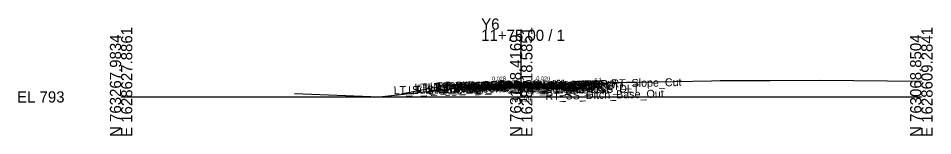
# Model space of a CAD drawing. Extents: x -26 to 203, y -10 to 6017.
# Drawn here: x -25.7 to 202.8, y 3490.3 to 3519.7 of the extents above; entities that cross this region are included whole.
import ezdxf

# ---------------------------------------------------------------- set-up
doc = ezdxf.new("R2010")
doc.units = 0
for name, color, linetype in [('Default', 7, 'Continuous'), ('Exist Cross Section Cell', 7, 'Continuous'), ('Exist XS Center Line Elevation Label', 7, 'Continuous'), ('Exist XS Ground Line', 7, 'Continuous'), ('Prop CMT Concrete Structures', 7, 'Continuous'), ('Prop CMT Pvmt Course 1', 7, 'Continuous'), ('Prop CMT Pvmt Course 2', 7, 'Continuous'), ('Prop CMT Pvmt Course 3', 7, 'Continuous'), ('Prop CMT Pvmt Surface', 7, 'Continuous'), ('Prop CMT Pvmt Surface Shoulder', 7, 'Continuous'), ('Prop CMT Pvmt Wedge Surface 2', 7, 'Continuous'), ('Prop CMT Pvmt Wedge Surface 3', 7, 'Continuous'), ('Prop CMT Shld Paved Course 1', 7, 'Continuous'), ('Prop CMT Shld Paved Course 2', 7, 'Continuous'), ('Prop CMT Shld Paved Course 3', 7, 'Continuous'), ('Prop CMT Slope Grass', 7, 'Continuous'), ('Prop CMT Subgrade Earthwork', 7, 'Continuous'), ('Prop XS SE Text', 7, 'Continuous'), ('Prop XS Side Slope Text', 7, 'Continuous'), ('Scratch_Level_0', 7, 'Continuous')]:
    doc.layers.add(name, color=color, linetype=linetype)

msp = doc.modelspace()

# ---------------------------------------------------------------- linework, layer by layer
at = {"layer": 'Exist Cross Section Cell'}
for p, q in [((100, 3500), (100, 3516.81)), ((0, 3500), (100, 3500)), ((100, 3500), (200, 3500))]:
    msp.add_line(p, q, dxfattribs=at)
at = {"layer": 'Exist XS Ground Line'}
msp.add_lwpolyline([(43.32, 3500.85), (64.56, 3500.04), (84.14, 3502.23), (89.22, 3502.94), (98.7, 3503.34), (100, 3503.39), (100.5, 3503.41), (102.9, 3503.38), (110.67, 3503.26), (112.66, 3503.27), (116.68, 3503.33), (124.6, 3503.6), (126.35, 3503.65), (128.35, 3503.71), (138.17, 3503.87), (147.55, 3504.05), (149.75, 3504.1), (162.15, 3504.13), (174.66, 3504.17), (200, 3503.98)], dxfattribs=at)
at = {"layer": 'Prop CMT Concrete Structures'}
msp.add_line((87, 3502.92), (82, 3503.02), dxfattribs=at)
for points in [[(87, 3502.92), (87, 3502.34), (89, 3502.34)], [(89, 3502.92), (88, 3502.84), (87, 3502.92)], [(89, 3502.34), (89, 3502.92)], [(111, 3502.42), (111, 3503.01)], [(113, 3503.01), (113, 3502.42), (111, 3502.42)], [(111, 3503.01), (112, 3502.92), (113, 3503.01)]]:
    msp.add_lwpolyline(points, dxfattribs=at)
at = {"layer": 'Prop CMT Pvmt Course 1'}
for points in [[(100, 3503.23), (89, 3502.92)], [(89, 3502.67), (100, 3502.98)], [(89, 3502.92), (89, 3502.67)], [(100, 3503.23), (89.22, 3502.93)], [(100, 3503.1), (100, 3503.23)], [(100, 3502.98), (100, 3503.23)], [(100, 3503.23), (110.67, 3503.01)], [(100, 3503.1), (100, 3503.23)], [(100, 3503.23), (111, 3503.01)], [(100, 3502.98), (100, 3503.23)], [(111, 3502.76), (100, 3502.98)], [(111, 3503.01), (111, 3502.76)]]:
    msp.add_lwpolyline(points, dxfattribs=at)
at = {"layer": 'Prop CMT Pvmt Course 2'}
for points in [[(100, 3502.98), (89, 3502.67)], [(89, 3502.67), (89, 3502.34)], [(89, 3502.34), (100, 3502.64)], [(100, 3502.64), (100, 3502.98)], [(100, 3502.64), (100, 3502.98)], [(100, 3502.98), (111, 3502.76)], [(111, 3502.42), (100, 3502.64)], [(111, 3502.76), (111, 3502.42)]]:
    msp.add_lwpolyline(points, dxfattribs=at)
at = {"layer": 'Prop CMT Pvmt Course 3'}
msp.add_line((113, 3502.42), (113.5, 3502.42), dxfattribs=at)
for points in [[(100, 3502.64), (89, 3502.34)], [(89, 3502.34), (89, 3502.01)], [(89, 3502.01), (100, 3502.31)], [(100, 3502.31), (100, 3502.64)], [(100, 3502.64), (111, 3502.42)], [(100, 3502.31), (100, 3502.64)], [(111, 3502.09), (100, 3502.31)], [(111, 3502.42), (111, 3502.09)]]:
    msp.add_lwpolyline(points, dxfattribs=at)
at = {"layer": 'Prop CMT Pvmt Surface'}
for points in [[(100, 3503.23), (89, 3502.92)], [(100, 3503.23), (89.22, 3502.93)], [(100, 3503.23), (111, 3503.01)], [(100, 3503.23), (110.67, 3503.01)]]:
    msp.add_lwpolyline(points, dxfattribs=at)
at = {"layer": 'Prop CMT Pvmt Surface Shoulder'}
for points in [[(89, 3502.92), (89, 3502.92)], [(111, 3503.01), (111, 3503.01)]]:
    msp.add_lwpolyline(points, dxfattribs=at)
at = {"layer": 'Prop CMT Pvmt Wedge Surface 2'}
for points in [[(100, 3502.98), (89.22, 3502.68)], [(100, 3502.98), (100, 3503.23)], [(100, 3502.98), (100, 3503.23)], [(100, 3502.98), (100, 3503.23)], [(100, 3502.98), (100, 3503.23)], [(100, 3502.98), (110.67, 3502.76)]]:
    msp.add_lwpolyline(points, dxfattribs=at)
at = {"layer": 'Prop CMT Pvmt Wedge Surface 3'}
for points in [[(100, 3502.64), (89.22, 3502.35)], [(100, 3502.64), (100, 3503.23)], [(100, 3502.64), (100, 3503.23)], [(100, 3502.64), (100, 3503.23)], [(100, 3502.64), (100, 3503.23)], [(100, 3502.64), (110.67, 3502.43)]]:
    msp.add_lwpolyline(points, dxfattribs=at)
at = {"layer": 'Prop CMT Shld Paved Course 1'}
for points in [[(89, 3502.92), (89, 3502.92)], [(89, 3502.67), (89, 3502.92)], [(111, 3503.01), (111, 3503.01)], [(111, 3502.76), (111, 3503.01)]]:
    msp.add_lwpolyline(points, dxfattribs=at)
at = {"layer": 'Prop CMT Shld Paved Course 2'}
for p, q in [((87, 3502.34), (89, 3502.34)), ((113, 3502.42), (111, 3502.42))]:
    msp.add_line(p, q, dxfattribs=at)
for points in [[(89, 3502.34), (89, 3502.67)], [(111, 3502.42), (111, 3502.76)]]:
    msp.add_lwpolyline(points, dxfattribs=at)
at = {"layer": 'Prop CMT Shld Paved Course 3'}
for p, q in [((86.16, 3502), (89, 3502.01)), ((113.84, 3502.08), (111, 3502.09))]:
    msp.add_line(p, q, dxfattribs=at)
for points in [[(89, 3502.34), (87, 3502.34), (86.5, 3502.34), (86.16, 3502)], [(89, 3502.01), (89, 3502.34)], [(111, 3502.09), (111, 3502.42)], [(111, 3502.42), (113.5, 3502.42), (113.5, 3502.42), (113.84, 3502.08)]]:
    msp.add_lwpolyline(points, dxfattribs=at)
at = {"layer": 'Prop CMT Slope Grass'}
for points in [[(113, 3503.01), (118, 3503.11), (120.98, 3503.48)], [(87, 3502.92), (82, 3503.02), (70, 3500.65)]]:
    msp.add_lwpolyline(points, dxfattribs=at)
at = {"layer": 'Prop CMT Subgrade Earthwork'}
for p, q in [((86.16, 3502), (85.2, 3502.96)), ((89, 3502.01), (86.16, 3502)), ((111, 3502.09), (113.84, 3502.08)), ((113.84, 3502.08), (114.8, 3503.04))]:
    msp.add_line(p, q, dxfattribs=at)
for points in [[(100, 3502.31), (89, 3502.01)], [(100, 3502.31), (111, 3502.09)]]:
    msp.add_lwpolyline(points, dxfattribs=at)

# ---------------------------------------------------------------- texts
at = {"layer": 'Default'}
msp.add_text('-', height=0.0001, dxfattribs=at).set_placement((0, 3500))
at = {"layer": 'Exist Cross Section Cell'}
for s, p in [('Y6', (90, 3516.81)), ('11+75.00 / 1', (90, 3514.01)), ('EL 793', (-26, 3498.6))]:
    msp.add_text(s, height=2.8, dxfattribs=at).set_placement(p)
for s, p in [('E 1628627.8861', (2.8, 3490)), ('E 1628618.5851', (102.8, 3490)), ('E 1628609.2841', (202.8, 3490)), ('N 763267.9834', (0, 3490)), ('N 763168.4169', (100, 3490)), ('N 763068.8504', (200, 3490))]:
    msp.add_text(s, height=2.8, rotation=90, dxfattribs=at).set_placement(p)
at = {"layer": 'Exist XS Center Line Elevation Label'}
msp.add_text('796.39', height=1.2, dxfattribs=at).set_placement((97.47, 3498.79))
at = {"layer": 'Prop XS SE Text'}
for s, rotation, p in [('0.028', 1.5752, (92.73, 3504.03)), ('0.020', 358.8542, (103.77, 3504.15))]:
    msp.add_text(s, height=1, rotation=rotation, dxfattribs=at).set_placement(p)
at = {"layer": 'Prop XS Side Slope Text'}
for s, rotation, p in [('5:1', 11.1865, (74.59, 3502.15)), ('8:1', 7.125, (118.37, 3503.63))]:
    msp.add_text(s, height=1, rotation=rotation, dxfattribs=at).set_placement(p)
at = {"layer": 'Scratch_Level_0'}
for s, p in [('LT_GS_OS_CTL', (73.39, 3501.31)), ('LT_PS3_Shelf_Out', (73.91, 3501.04)), ('LT_PV2_OEEOP_W', (76.66, 3501.43)), ('LT_PV3_OEEOP_W', (76.66, 3501.09)), ('LT_PV1_OEEOP_W', (77.22, 3501.56)), ('LT_PS3_OEOP', (78.66, 3501.13)), ('LT_PS2_OEOP', (79, 3501.47)), ('LT_PV1_OEEOP', (79.11, 3501.73)), ('LT_PV2_OEOT', (79.2, 3501.48)), ('LT_PV3_OEOT', (79.2, 3501.14)), ('LT_PV1_OEOT', (79.76, 3501.74)), ('LT_PS1_OEOP', (79.82, 3501.74)), ('RT_PV1_PGL_W', (89.86, 3501.9)), ('LT_PV1_PGL_W', (89.91, 3501.9)), ('PV2_PGL', (93.93, 3501.85)), ('PV3_PGL', (93.93, 3501.52)), ('PV1_PGL', (94.49, 3502.12)), ('RT_PS3_Shelf_Out', (98.06, 3501.12)), ('RT_PV2_OEEOP_W', (98.06, 3501.51)), ('RT_PV3_OEEOP_W', (98.06, 3501.18)), ('RT_PV1_OEEOP_W', (98.63, 3501.65)), ('RT_PV1_OEEOP', (100.52, 3501.81)), ('RT_PV2_OEOT', (101.15, 3501.56)), ('RT_PV3_OEOT', (101.15, 3501.23)), ('RT_PS2_OEOP', (101.47, 3501.55)), ('RT_PV1_OEOT', (101.71, 3501.82)), ('RT_PS1_OEOP', (101.78, 3501.82)), ('RT_PS3_OEOP', (101.81, 3501.21)), ('RT_GS_OS_CTL', (105.34, 3501.39)), ('RT_Slope_Cut', (122.54, 3502.37)), ('LT_Sub_OSS_DLT', (68.14, 3500.66)), ('LT_Sub_Trench_Out', (71.79, 3500.66)), ('LT_Sub_OEOT', (79.1, 3500.81)), ('Sub_PGL', (93.83, 3501.19)), ('RT_Sub_Trench_Out', (96.62, 3500.74)), ('RT_Sub_OEOT', (101.05, 3500.89)), ('RT_SS_Ditch_Base_Out', (106.06, 3499.25)), ('RT_Sub_OSS_DLT', (106.06, 3500.68))]:
    msp.add_text(s, height=2, rotation=1.1458, dxfattribs=at).set_placement(p)

doc.saveas('drawing.dxf')
